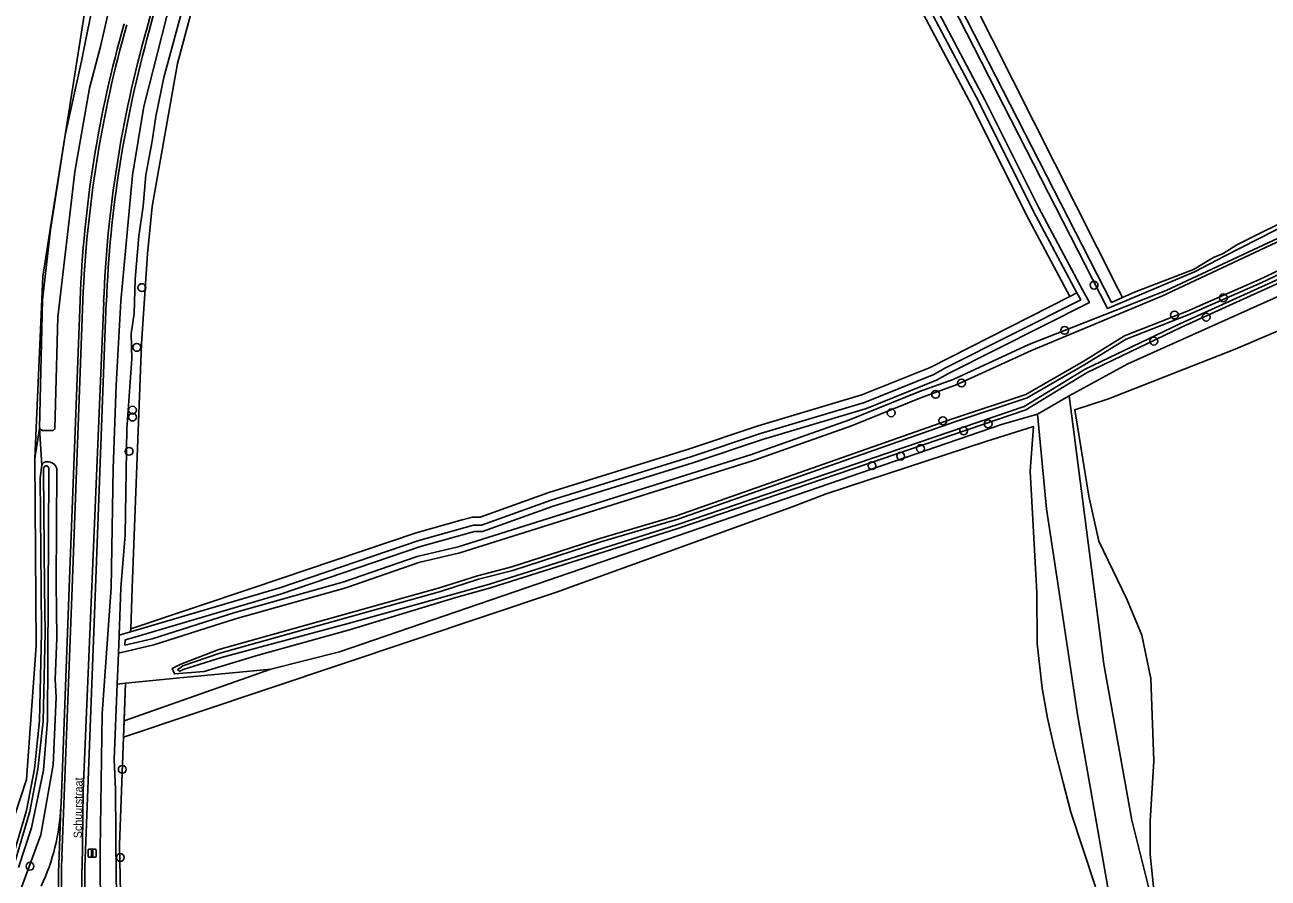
# Model space of a CAD drawing. Extents: x 164494 to 166241, y 382475 to 384494.
# Drawn here: x 165159.3 to 165314.6, y 383463.7 to 383570.3 of the extents above; entities that cross this region are included whole.
import ezdxf

# ---------------------------------------------------------------- set-up
doc = ezdxf.new("R2010")
doc.units = 0
for name, color, linetype in [('IMGEO_Boom', 7, 'Continuous'), ('IMGEO_Grasland_agrarisch', 7, 'Continuous'), ('IMGEO_Grasland_overig', 7, 'Continuous'), ('IMGEO_Groenvoorziening', 7, 'Continuous'), ('IMGEO_Hek', 7, 'Continuous'), ('IMGEO_Loofbos', 7, 'Continuous'), ('IMGEO_Openbare_ruimte_label', 7, 'Continuous'), ('IMGEO_Rijbaan_lokaal_gesloten', 7, 'Continuous'), ('IMGEO_Rijbaan_lokaal_halfverhard', 7, 'Continuous'), ('IMGEO_Rijbaan_lokaal_open', 7, 'Continuous'), ('IMGEO_Verkeersbordpaal', 7, 'Continuous'), ('IMGEO_Waterloop', 7, 'Continuous')]:
    doc.layers.add(name, color=color, linetype=linetype)

msp = doc.modelspace()

# ---------------------------------------------------------------- linework, layer by layer
at = {"layer": 'IMGEO_Boom'}
for centre in [(165173.91, 383537.5), (165292.88, 383537.81), (165309.04, 383536.22), (165302.93, 383534.07), (165306.89, 383533.81), (165289.2, 383532.16), (165300.35, 383530.82), (165173.28, 383530.03), (165273.08, 383524.17), (165276.32, 383525.58), (165172.74, 383522.2), (165172.74, 383521.33), (165267.53, 383521.86), (165273.99, 383520.87), (165276.58, 383519.61), (165279.64, 383520.48), (165172.31, 383517.05), (165268.72, 383516.45), (165271.19, 383517.4), (165265.14, 383515.26), (165171.46, 383477.34), (165159.93, 383465.23), (165171.22, 383466.32)]:
    msp.add_circle(centre, 0.489, dxfattribs=at)
at = {"layer": 'IMGEO_Grasland_agrarisch'}
for points in [[(165180.48, 383573.45), (165178.36, 383565.49), (165175.18, 383547.62), (165174.6, 383541.72), (165173.86, 383530.47), (165172.71, 383500), (165172.52, 383494.9)], [(165289.85, 383536.4), (165284.4, 383546.64), (165277.63, 383560.15), (165271.18, 383572.32)], [(165296.44, 383536.25), (165297.94, 383536.93), (165305.29, 383539.77), (165307.81, 383541.25), (165309.03, 383541.76), (165310.73, 383542.84), (165318.85, 383546.88), (165332.79, 383552.6), (165348.13, 383559.43), (165351.61, 383560.48), (165353.13, 383561.14), (165353.25, 383560.96), (165353.42, 383559.18)], [(165180.33, 383434.03), (165174.49, 383445.04), (165172.15, 383452.22), (165171.27, 383459.97), (165171.1, 383467.92), (165171.62, 383481.35)]]:
    msp.add_lwpolyline(points, dxfattribs=at)
at = {"layer": 'IMGEO_Grasland_overig'}
for points in [[(165164.33, 383556.52), (165167.42, 383576.04), (165107.84, 383587.32), (165107.52, 383585.73), (165088.86, 383468.79), (165088.13, 383468.87)], [(165365.07, 383538.16), (165362.3, 383549.17), (165361.59, 383551), (165361.14, 383551.18), (165360.22, 383551.01), (165310.5, 383529.81), (165294.69, 383523.59), (165290.46, 383522.24), (165292.24, 383511.44), (165293.47, 383505.85), (165296.98, 383498.6), (165298.86, 383494.09), (165299.97, 383488.69), (165300.34, 383478.38), (165299.89, 383470.85), (165299.89, 383466.7), (165300.46, 383461.04), (165300.48, 383459.49)], [(165171.62, 383481.35), (165225.7, 383499.47), (165255.27, 383510.18), (165259.4, 383511.74), (165279.34, 383518.27), (165285.33, 383520.14), (165284.88, 383514.57), (165285.75, 383499.4), (165285.76, 383493.03), (165286.4, 383487.49), (165287.05, 383483.71), (165287.95, 383479.89), (165289.01, 383475.68), (165289.97, 383471.99), (165293.05, 383462.67)], [(165161.13, 383519.91), (165160.54, 383516.17), (165160.71, 383492.77), (165159.48, 383476.07), (165153.4, 383457.64), (165151.58, 383456.21), (165146.12, 383454.14), (165137.71, 383452.81), (165120.5, 383455.57), (165087.6, 383460.85), (165085.8, 383461.14)], [(165161.4, 383515.31), (165161.13, 383519.91)], [(165140.5, 383452.79), (165144.46, 383453.15), (165150, 383454.98), (165152.73, 383456.51), (165155.13, 383460.13), (165157.46, 383465.3), (165159.51, 383472.18), (165160.48, 383477.41), (165161.14, 383483.39), (165161.38, 383494.41), (165161.32, 383500), (165161.2, 383513.73), (165161.4, 383515.31)], [(165171.62, 383481.35), (165171.7, 383483.38)]]:
    msp.add_lwpolyline(points, dxfattribs=at)
at = {"layer": 'IMGEO_Groenvoorziening'}
for points in [[(165290.74, 383536.85), (165285.29, 383547.1), (165278.52, 383560.61), (165272.07, 383572.78), (165252.26, 383612.09), (165251.9, 383612.66), (165251.49, 383613.2), (165251.04, 383613.71), (165250.54, 383614.17), (165250.01, 383614.59), (165249.44, 383614.96), (165248.85, 383615.27), (165248.22, 383615.54), (165242.65, 383617.16), (165229.94, 383620.21), (165228.11, 383624.66)], [(165163.28, 383514.89), (165163.21, 383500.58), (165163.28, 383493.74), (165163.08, 383488.57), (165163.22, 383486.35), (165162.84, 383477.91), (165161.29, 383469.15), (165158.61, 383461.9), (165155.95, 383457.11), (165151.54, 383452.4), (165149.63, 383451.59), (165148.18, 383450.97), (165144.44, 383450.23), (165140.63, 383450.13), (165140.56, 383451.5), (165140.5, 383452.79)], [(165171.06, 383494.09), (165172.5, 383494.51)]]:
    msp.add_lwpolyline(points, dxfattribs=at)
for centre, radius, start, end in [((165162, 383515.1), 0.635, 80.9352, 160.7513), ((165162.18, 383514.6), 1.13, 14.701, 94.1869)]:
    msp.add_arc(centre, radius, start, end, dxfattribs=at)
at = {"layer": 'IMGEO_Hek'}
for points in [[(165295.91, 383537.31), (165272.21, 383584.36), (165254.77, 383618.97), (165251.77, 383621.08), (165247.82, 383622.29), (165228.83, 383625.73), (165227.32, 383629.36)], [(165064.91, 383595.43), (165078.35, 383592.91), (165167.42, 383576.04), (165164.33, 383556.52)], [(165172.52, 383494.9), (165172.71, 383500), (165173.86, 383530.47), (165174.6, 383541.72), (165175.18, 383547.62), (165178.36, 383565.49), (165180.48, 383573.45)], [(165271.18, 383572.32), (165277.63, 383560.15), (165284.4, 383546.64), (165289.85, 383536.4)], [(165164.33, 383556.52), (165162.5, 383545.03)], [(165162.5, 383545.03), (165161.53, 383538.9), (165160.54, 383516.17), (165160.71, 383492.77), (165159.48, 383476.07), (165153.4, 383457.64), (165151.58, 383456.21), (165146.12, 383454.14), (165137.71, 383452.81), (165120.5, 383455.57)], [(165289.85, 383536.4), (165272.42, 383527.54), (165263.86, 383524.12), (165250.9, 383520.22), (165242.2, 383517.32), (165224.74, 383511.92), (165216.18, 383508.81), (165215.24, 383508.81), (165213.92, 383508.51), (165208.2, 383506.89), (165187.83, 383500), (165172.52, 383494.9)], [(165285.82, 383521.7), (165286.94, 383509.86), (165288.43, 383500), (165290.82, 383484.2), (165294.74, 383461.86), (165302.55, 383424.01), (165297.87, 383419.71), (165258.94, 383400.42), (165249.62, 383397.98), (165236.2, 383390.63), (165225.01, 383383.11), (165185.99, 383428.78), (165180.33, 383434.03)], [(165178.24, 383488.7), (165190.04, 383489.85), (165198.6, 383491.99), (165221.91, 383500), (165281.33, 383520.4)], [(165180.33, 383434.03), (165174.49, 383445.04), (165172.15, 383452.22), (165171.27, 383459.97), (165171.1, 383467.92), (165171.88, 383488.09)], [(165171.88, 383488.09), (165178.24, 383488.7)]]:
    msp.add_lwpolyline(points, dxfattribs=at)
at = {"layer": 'IMGEO_Loofbos'}
for points in [[(165227.32, 383629.36), (165228.83, 383625.73), (165247.82, 383622.29), (165251.77, 383621.08), (165254.77, 383618.97), (165272.21, 383584.36), (165295.91, 383537.31), (165296.44, 383536.25)], [(165228.11, 383624.66), (165245.49, 383620.41), (165249.65, 383619.24), (165250.39, 383618.92), (165251.1, 383618.54), (165251.78, 383618.09), (165252.41, 383617.59), (165252.99, 383617.03), (165253.53, 383616.42), (165254.01, 383615.78), (165254.42, 383615.08), (165295.06, 383535.64), (165296.44, 383536.25)], [(165289.76, 383523.98), (165297.08, 383527.98), (165337.14, 383545.92), (165361.9, 383556.33), (165366.29, 383558.17), (165403.93, 383575.26), (165412.1, 383577.98)], [(165353.42, 383559.18), (165352.62, 383559.04), (165351.66, 383558.44), (165339.1, 383553.33), (165336.12, 383552.26), (165331.16, 383549.95), (165324.1, 383547.27), (165318.38, 383544.44), (165301.45, 383536.48), (165285.06, 383529.66), (165275.58, 383525.3), (165271.33, 383523.79), (165262.59, 383520.24), (165250.33, 383515.91), (165213.62, 383504.36), (165208.52, 383503.17), (165199.38, 383500), (165185.61, 383496.13), (165175.39, 383492.88), (165170.97, 383491.86)], [(165317.92, 383538.96), (165303.8, 383532.57), (165292, 383526.91), (165284.34, 383522.25), (165240.89, 383507.42), (165217.48, 383500), (165213.14, 383498.81), (165199.86, 383494.74), (165188.42, 383491.59), (165181.68, 383489.55), (165177.98, 383489.26), (165177.69, 383489.91), (165178.76, 383490.47), (165183.52, 383492.28), (165211.09, 383500), (165215.85, 383501.52), (165220.12, 383502.61), (165231.13, 383506.17), (165240.71, 383509), (165275.19, 383521.12), (165284.35, 383524.15), (165291.5, 383528.28), (165296.69, 383531.48), (165304.45, 383534.5), (165313.55, 383538.5), (165326.27, 383544.56)], [(165172.5, 383494.51), (165191.13, 383500), (165208.5, 383505.93), (165215.36, 383507.81), (165216.34, 383507.81), (165225.06, 383510.97), (165242.5, 383516.37), (165251.21, 383519.27), (165264.19, 383523.17), (165272.85, 383526.63), (165274.33, 383527.49), (165291.21, 383535.97), (165290.74, 383536.85)], [(165172.52, 383494.9), (165187.83, 383500), (165208.2, 383506.89), (165213.92, 383508.51), (165215.24, 383508.81), (165216.18, 383508.81), (165224.74, 383511.92), (165242.2, 383517.32), (165250.9, 383520.22), (165263.86, 383524.12), (165272.42, 383527.54), (165289.85, 383536.4)], [(165289.85, 383536.4), (165290.74, 383536.85)], [(165285.82, 383521.7), (165289.76, 383523.98)], [(165289.76, 383523.98), (165293.02, 383498.86), (165294.11, 383490.45), (165297.58, 383470.97), (165300.48, 383459.49)], [(165171.7, 383483.38), (165190.04, 383489.85), (165198.6, 383491.99), (165221.91, 383500), (165281.33, 383520.4), (165285.82, 383521.7)], [(165285.82, 383521.7), (165286.94, 383509.86), (165288.43, 383500), (165290.82, 383484.2), (165294.74, 383461.86), (165302.55, 383424.01), (165297.87, 383419.71), (165258.94, 383400.42), (165249.62, 383397.98), (165236.2, 383390.63), (165225.01, 383383.11), (165185.99, 383428.78)], [(165172.5, 383494.51), (165172.52, 383494.9)], [(165170.82, 383487.96), (165171.88, 383488.09), (165171.7, 383483.38)]]:
    msp.add_lwpolyline(points, dxfattribs=at)
at = {"layer": 'IMGEO_Rijbaan_lokaal_gesloten'}
for points in [[(165163.93, 383466.45), (165165.19, 383500), (165166.54, 383535.92)], [(165166.43, 383464.86), (165166.59, 383474.65), (165167.66, 383500.11), (165169.14, 383535.72)]]:
    msp.add_lwpolyline(points, dxfattribs=at)
for centre, radius, start, end in [((165452.36, 383499.04), 286.71, 160.5453, 165.738), ((165315.78, 383529.82), 149.36, 164.2685, 177.6594), ((165314.41, 383530.21), 145.38, 164.2486, 177.83), ((165216.54, 383463.68), 52.68, 176.9906, 211.8343), ((165217.17, 383463.81), 50.76, 178.814, 211.8859)]:
    msp.add_arc(centre, radius, start, end, dxfattribs=at)
at = {"layer": 'IMGEO_Rijbaan_lokaal_halfverhard'}
msp.add_arc((165137.85, 383473.85), 25.97, 334.7066, 357.3977, dxfattribs=at)
at = {"layer": 'IMGEO_Rijbaan_lokaal_open'}
for points in [[(165166.19, 383535.94), (165164.83, 383500), (165163.81, 383473.09), (165163.8, 383472.67)], [(165166.83, 383466.16), (165168.12, 383500), (165169.47, 383535.67)], [(165163.8, 383472.67), (165163.57, 383466.51)]]:
    msp.add_lwpolyline(points, dxfattribs=at)
for centre, radius, start, end in [((165377.01, 383520.3), 208.09, 159.0691, 166.3059), ((165311.12, 383530.5), 145.03, 164.0113, 177.8491), ((165315.86, 383529.88), 146.5, 164.2848, 177.7375), ((165216.67, 383463.69), 53.18, 176.9597, 211.7457), ((165216.77, 383463.74), 49.99, 177.2243, 212.0888)]:
    msp.add_arc(centre, radius, start, end, dxfattribs=at)
at = {"layer": 'IMGEO_Verkeersbordpaal'}
for p, q in [((165167.21, 383466.47), (165167.21, 383467.27)), ((165167.21, 383467.27), (165167.21, 383466.47)), ((165167.31, 383467.37), (165168.1, 383467.37)), ((165168.1, 383467.37), (165167.31, 383467.37)), ((165168.2, 383467.27), (165168.2, 383466.47)), ((165168.2, 383466.47), (165168.2, 383467.27)), ((165168.1, 383466.37), (165167.31, 383466.37)), ((165167.31, 383466.37), (165168.1, 383466.37))]:
    msp.add_line(p, q, dxfattribs=at)
msp.add_lwpolyline([(165167.63, 383467.24), (165167.78, 383467.24), (165167.78, 383466.49), (165167.63, 383466.49), (165167.63, 383467.24)], dxfattribs=at)
for centre, start, end in [((165167.31, 383467.27), 90, 180), ((165167.31, 383467.27), 90, 180), ((165168.1, 383467.27), 0, 90), ((165168.1, 383467.27), 360, 90), ((165167.31, 383466.47), 180, 270), ((165167.31, 383466.47), 180, 270), ((165168.1, 383466.47), 270, 0), ((165168.1, 383466.47), 270, 0)]:
    msp.add_arc(centre, 0.1, start, end, dxfattribs=at)
at = {"layer": 'IMGEO_Waterloop'}
for points in [[(165319.65, 383546.76), (165309.18, 383541.43), (165305.44, 383539.48), (165294.56, 383534.87), (165253.73, 383614.7)], [(165171.06, 383494.09), (165171.3, 383500), (165171.84, 383506.61), (165172.02, 383519.84), (165172.64, 383528.6), (165172.59, 383531.72), (165172.95, 383534.28), (165173.08, 383538.54), (165173.53, 383543.94), (165174.06, 383547.66), (165174.41, 383551.58), (165175.21, 383555.79), (165175.64, 383558.87), (165176.67, 383563.73), (165179.05, 383572.6), (165182.49, 383581.46)], [(165179.44, 383579.9), (165178.7, 383578), (165174.14, 383560.1), (165172.75, 383551.56), (165171.27, 383535.82), (165170.7, 383525.31), (165170.31, 383514.89), (165170.06, 383500), (165168.97, 383484.32), (165168.72, 383467.34), (165168.76, 383458.42), (165169.05, 383455.04), (165169.28, 383453.05), (165169.73, 383450.81), (165170.24, 383448.79), (165171.08, 383448.15), (165171.95, 383448.11), (165172.01, 383448.23)], [(165161.13, 383519.91), (165161.45, 383519.65), (165162.83, 383519.67), (165163.04, 383519.85), (165163.43, 383533.8), (165165.53, 383551.96), (165167.37, 383562.39), (165168.76, 383567.63), (165170.71, 383576.2)], [(165164.33, 383556.52), (165166.35, 383565.77), (165167.07, 383569.32), (165167.77, 383572.79), (165168.46, 383576.5)], [(165272.78, 383573.14), (165279.22, 383560.97), (165285.99, 383547.46), (165291.44, 383537.22), (165292.29, 383535.62), (165274.71, 383526.79), (165273.2, 383525.92), (165264.45, 383522.42), (165251.45, 383518.51), (165242.75, 383515.61), (165225.31, 383510.22), (165216.48, 383507.02), (165215.46, 383507.02), (165208.73, 383505.17), (165191.37, 383499.25), (165172.73, 383493.75), (165171.83, 383493.49), (165171.8, 383492.86), (165175.18, 383493.64), (165185.38, 383496.89), (165199.15, 383500.76), (165208.3, 383503.93), (165213.41, 383505.12), (165250.08, 383516.66), (165262.31, 383520.98), (165271.05, 383524.53), (165275.28, 383526.04), (165284.74, 383530.39), (165289.2, 383532.16), (165301.89, 383537.12)], [(165161.13, 383519.91), (165161.5, 383535.99), (165162.48, 383544.71), (165164.33, 383556.52)], [(165178.36, 383489.75), (165179.01, 383490.28), (165183.66, 383491.85), (165211.22, 383499.56), (165215.97, 383501.08), (165220.25, 383502.17), (165231.27, 383505.74), (165240.86, 383508.57), (165275.34, 383520.69), (165284.53, 383523.73), (165291.73, 383527.89), (165296.89, 383531.08), (165304.62, 383534.08), (165313.74, 383538.08), (165326.46, 383544.15)], [(165301.89, 383537.12), (165317.82, 383544.58)], [(165317.74, 383539.38), (165303.61, 383532.98), (165291.78, 383527.31), (165284.14, 383522.66), (165240.74, 383507.85), (165217.35, 383500.44), (165213.01, 383499.24), (165199.68, 383495.53), (165188.19, 383492.47), (165183.86, 383491.29), (165179.09, 383489.82), (165178.64, 383489.59), (165178.36, 383489.75)], [(165162.3, 383514.46), (165162.3, 383514.58), (165162.3, 383514.7), (165162.29, 383514.81), (165162.27, 383514.92), (165162.24, 383515.02), (165162.19, 383515.11), (165162.11, 383515.19), (165162.03, 383515.24), (165161.93, 383515.25), (165161.8, 383515.21), (165161.74, 383515.16), (165161.69, 383515.07), (165161.65, 383514.97), (165161.63, 383514.81), (165161.62, 383514.74), (165161.62, 383514.64), (165161.62, 383514.54), (165161.76, 383500), (165161.81, 383494.41), (165161.57, 383483.36), (165160.91, 383477.35), (165159.93, 383472.08), (165157.86, 383465.15)], [(165158.48, 383465.09), (165160.1, 383470.02), (165161.61, 383477.23), (165162.14, 383483.44), (165162.3, 383514.46)], [(165170.97, 383491.86), (165171.06, 383494.09)], [(165170.82, 383487.96), (165170.97, 383491.86)], [(165172.01, 383448.23), (165172.23, 383448.63), (165171.72, 383451.29), (165171.27, 383453.5), (165170.98, 383455.43), (165170.71, 383463.63), (165170.61, 383474.87), (165170.44, 383478.55), (165170.82, 383487.96)]]:
    msp.add_lwpolyline(points, dxfattribs=at)

# ---------------------------------------------------------------- texts
at = {"layer": 'IMGEO_Openbare_ruimte_label'}
msp.add_text('Schuurstraat', height=1, rotation=89.1406, dxfattribs=at).set_placement((165166.39, 383468.73))

doc.saveas('drawing.dxf')
